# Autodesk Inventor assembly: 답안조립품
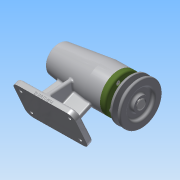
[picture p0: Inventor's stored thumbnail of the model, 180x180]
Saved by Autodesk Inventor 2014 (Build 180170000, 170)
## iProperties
Created: 2018-09
Part Number: 답안조립품
Document SubType Name: Assembly
Designer: 701-16
Author: 701-16
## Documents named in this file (12)
- C:\Users\701-16\Desktop\480908V1005\답안조립품.iam
- C:\Users\701-16\Desktop\480908V1005\본체.ipt
- C:\Users\701-16\Desktop\480908V1005\베어링 6004.ipt
- C:\Users\701-16\Desktop\480908V1005\베어링 51202.ipt
- C:\Users\701-16\Desktop\480908V1005\축.ipt
- C:\Users\701-16\Desktop\480908V1005\어댑터슬리브.ipt
- C:\Users\701-16\Desktop\480908V1005\볼트 M4.ipt
- C:\Users\701-16\Desktop\480908V1005\오일 실.ipt
- C:\Users\701-16\Desktop\480908V1005\커버.ipt
- C:\Users\701-16\Desktop\480908V1005\키 5 x 5 x 16.ipt
- C:\Users\701-16\Desktop\480908V1005\V벨트풀리.ipt
- C:\Users\701-16\Desktop\480908V1005\멈춤나사 M3.ipt
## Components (1 placed, 1 different names)
1. V벨트풀리:1
